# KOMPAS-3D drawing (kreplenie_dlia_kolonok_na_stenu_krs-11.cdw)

Views: Спереди 1, Проекционный вид 3, Вид 4, Вид 5
Referenced files: Крон.cdw
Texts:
  КРC-11
  Крепление для акустических колонок
  Никита
  Комплектность
  крепления колонок
  Хомуты
  Поворотный кронштейн
  с крепежом
  Кронштейн
  любой размер
  Любой диаметр
  Изготавливаем кронштейны для крепления акустических колонок
  на столб или на стену по стандартным чертежам, а также по
  вашим размерам.
  Покрытие: Порошковая покраска / Ц6хр / Горячее цинкование.
  POLYLINE_STYLE_0.18_RGB_0_0_0
  ООО "Центр инженерных
  услуг "МОДЕЛЬЕР"
  Крепление для
  акустических колонок
Dimensions and other numbers on the sheet: 300; 220; 100; 12; 4 отв.; 500; 1:4; 2216.01.00.003-; 1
